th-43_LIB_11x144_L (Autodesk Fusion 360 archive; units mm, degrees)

design "th-43_LIB_11x144_L" references "temple_stock"
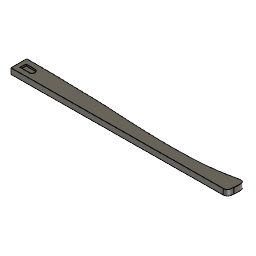
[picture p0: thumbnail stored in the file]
sketch "Temple_Left" plane through (0, 0, 0) normal (0, 0, 1) x axis (1, 0, 0)
  line L1 (0, 0) -> (3, 0)
  line L2 (10, 2) -> (3.3, 2)
  line L3 (2.7, -2) -> (3.3, 2)
  line L4 (2.7, -2) -> (10, -2)
  curve K1 (149.4284, 0) -> (0, 5.5)
  curve K2 (33.1105, 5.5) -> (-33.1105, 5.5)
  curve K3 (50.3491, 4.7282) -> (26.9792, 5.1746)
  curve K4 (137.2912, 3.2039) -> (79.9443, 2.2873)
  curve K5 (148.5188, -9.5484) -> (150.338, 9.5484)
  line L5 (146.6432, -4.3396) -> (0, -5.5)
  curve K6 (149.4284, 0) -> (145.0949, -4.3519)
  curve K7 (146.4141, -4.4073) -> (143.7756, -4.2964)
  curve K8 (149.5275, 1.268) -> (149.3294, -1.268)
  line L6 (0, 5.5) -> (0, -5.5)
  arc A1 centre (9.1115, 0) radius 2.1885 between (10, -2) and (10, 2)
  point P7 (3, 0)
  point P4 (0, 0)
  midpoint P7 L3
  dimension "d27" distance P4 P7 = 3
  dimension "d24" TaperAngle = 0
  dimension "d22" distance = 6.1
  dimension "d23" AlongDistance = -1.1
extrude "Extrude7" new body sketch "Temple_Left" profile of A1 L2 L3 L4 K1 L5 K6 L6 along normal blind 4
extrude "Extrude8" add sketch "Temple_Left" profile of A1 L2 L3 L4 along normal blind 2.95
component_insert "Component Insert"

design "temple_stock"
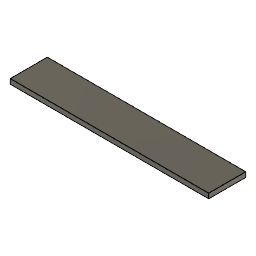
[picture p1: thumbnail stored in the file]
sketch "30mm Temple Blank" plane through (0, 0, 0) normal (0, 0, 1) x axis (1, 0, 0)
  line L1 (160, 15) -> (0, 15)
  line L2 (160, -15) -> (160, 15)
  line L3 (0, -15) -> (160, -15)
  line L4 (0, 15) -> (0, -15)
  point P2 (0, 15)
  point P3 (160, 15)
  point P5 (0, -15)
  horizontal L1
  vertical L2
  horizontal L3
  vertical L4
  dimension "d1" distance P2 P3 = 160
  dimension "d2" distance P2 P5 = 30
sketch "135mm Core Guide" plane through (0, 0, 0) normal (0, 0, 1) x axis (1, 0, 0)
  line L1 (135, 0) -> (0, 0)
  point P1 (0, 0)
  point P2 (0, 0)
  point P3 (135, 0)
  coincident P1 P2
  horizontal L1
  dimension "d4" distance P2 P3 = 135
sketch "140mm Core Guide" plane through (0, 0, 0) normal (0, 0, 1) x axis (1, 0, 0)
  line L1 (140, 0) -> (0, 0)
  point P1 (0, 0)
  point P2 (0, 0)
  point P3 (140, 0)
  coincident P1 P2
  horizontal L1
  dimension "d5" distance P2 P3 = 140
sketch "145mm Core Guide" plane through (0, 0, 0) normal (0, 0, 1) x axis (1, 0, 0)
  line L1 (145, 0) -> (0, 0)
  point P1 (0, 0)
  point P2 (0, 0)
  point P3 (145, 0)
  coincident P1 P2
  horizontal L1
  dimension "d6" distance P2 P3 = 145
extrude "Extrude1" new body sketch "30mm Temple Blank" along normal blind 4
